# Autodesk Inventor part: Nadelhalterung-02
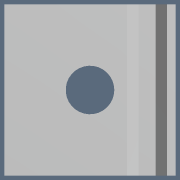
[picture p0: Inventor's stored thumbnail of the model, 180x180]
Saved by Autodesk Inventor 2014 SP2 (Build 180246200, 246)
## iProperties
Created: 2014-04
Part Number: Nadelhalterung-02
Project: Verstellbarer Werkstückanschlag
Material: Aluminium 6061
Document SubType Name: Modeling
Designer: e_dammj
Density: 2.71 g/cm^3
Appearance: Aluminium - flach
Company: VDW-Nachwuchsstiftung
Author: e_dammj
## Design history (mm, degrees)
derived "Nadelhalterung.ipt"
feature "Volumenkörper1::Nadelhalterung.ipt"
tag "Bezeichnung1"
node "Volumenkörper1"
other parameters: "d3" = 0, "d4" = 15, "d5" = 3, "d6" = 0, "d7" = 8.5, "d9" = 13.5, "d10" = 8.5, "d15" = 3, "d17" = 1, "d18" = 3, "d19" = 45 deg, "d21" = 0, "d23" = 0, "d24" = 12.5
